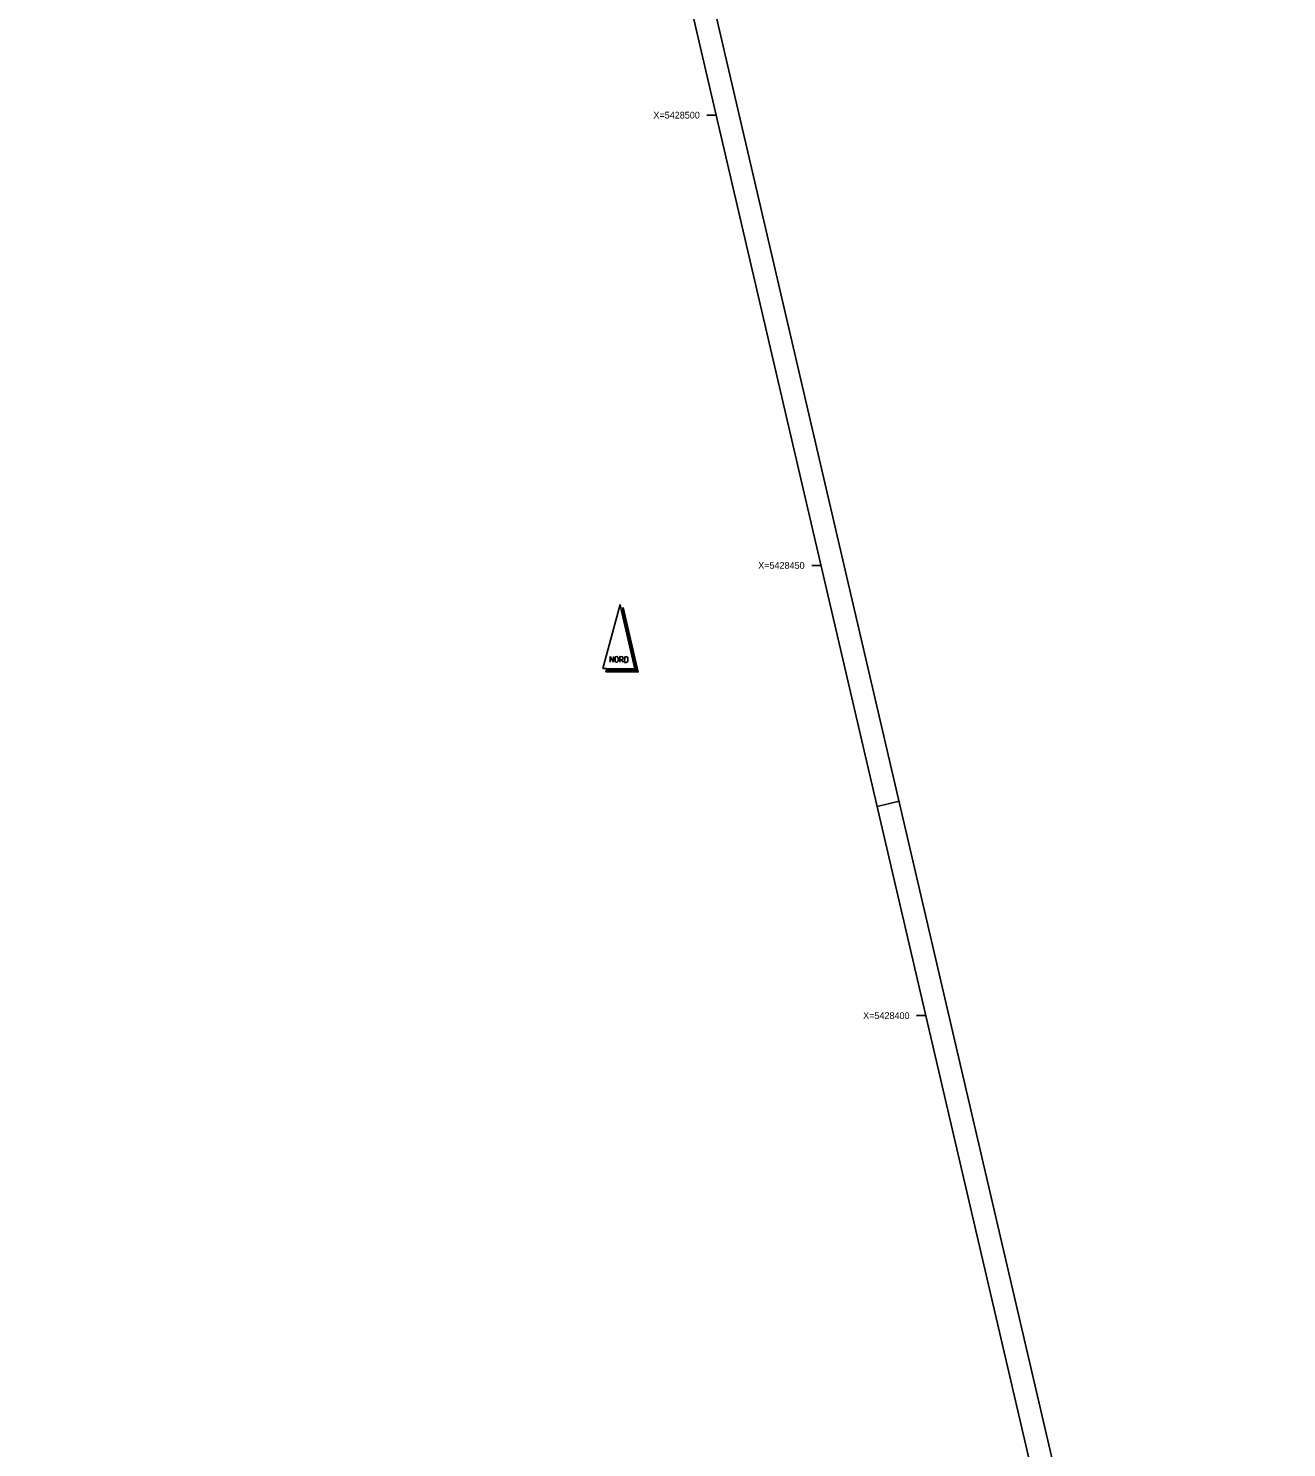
# Model space of a CAD drawing. Extents: x 3455797 to 3456077, y 5428205 to 5428818.
# Drawn here: x 3455936.9 to 3456076.6, y 5428352 to 5428509.6 of the extents above; entities that cross this region are included whole.
import ezdxf

# ---------------------------------------------------------------- set-up
doc = ezdxf.new("R2010")
doc.units = 0
for name, color, linetype in [('_GINETZ', 7, 'Continuous'), ('Nordpfeil', 7, 'Continuous'), ('Planrahmen', 7, 'Continuous')]:
    doc.layers.add(name, color=color, linetype=linetype)

# ---------------------------------------------------------------- blocks, each defined once
blk = doc.blocks.new('_X')
at = {"layer": 'Default'}
for p, q in [((-9.050951, -0.03534), (-9.044004, -0.028392)), ((-9.050951, -0.053017), (-9.029862, -0.031928)), ((-9.050951, -0.070695), (-9.01572, -0.035464)), ((-9.050951, -0.088373), (-9.001578, -0.038999)), ((-9.050951, -0.106051), (-8.987435, -0.042535)), ((-9.050951, -0.123728), (-8.973293, -0.04607)), ((-9.050951, -0.141406), (-8.959151, -0.049606)), ((-9.050951, -0.159084), (-8.948451, -0.056584)), ((-9.050951, -0.176761), (-8.948451, -0.074261)), ((-9.050951, -0.194439), (-8.948451, -0.091939)), ((-9.050951, -0.212117), (-8.948451, -0.109617)), ((-9.050951, -0.229794), (-8.948451, -0.127294)), ((-9.050951, -0.247472), (-8.948451, -0.144972)), ((-9.050951, -0.26515), (-8.948451, -0.16265)), ((-9.050951, -0.282827), (-8.948451, -0.180327)), ((-9.050951, -0.300505), (-8.948451, -0.198005)), ((-9.050951, -0.318183), (-8.948451, -0.215683)), ((-9.050951, -0.33586), (-8.948451, -0.23336)), ((-9.050951, -0.353538), (-8.948451, -0.251038)), ((-9.050951, -0.371216), (-8.948451, -0.268716)), ((-9.050951, -0.388893), (-8.948451, -0.286393)), ((-9.050951, -0.406571), (-8.948451, -0.304071)), ((-9.050951, -0.424249), (-8.948451, -0.321749)), ((-9.050951, -0.441926), (-8.948451, -0.339426)), ((-9.050951, -0.459604), (-8.948451, -0.357104)), ((-9.050951, -0.477282), (-8.948451, -0.374782)), ((-9.050951, -0.494959), (-8.948451, -0.392459)), ((-9.050951, -0.512637), (-8.948451, -0.410137)), ((-9.050951, -0.530315), (-8.948451, -0.427815)), ((-9.050951, -0.547992), (-8.948451, -0.445492)), ((-9.050951, -0.56567), (-8.948451, -0.46317)), ((-9.050951, -0.583348), (-8.948451, -0.480848)), ((-9.050951, -0.601025), (-8.948451, -0.498525)), ((-9.050951, -0.618703), (-8.948451, -0.516203)), ((-9.050951, -0.636381), (-8.948451, -0.533881)), ((-9.050951, -0.654058), (-8.948451, -0.551558)), ((-9.050951, -0.671736), (-8.948451, -0.569236)), ((-9.050951, -0.689414), (-8.948451, -0.586914)), ((-9.050951, -0.707091), (-8.948451, -0.604591)), ((-9.050951, -0.724769), (-8.948451, -0.622269)), ((-9.050951, -0.742447), (-8.948451, -0.639947)), ((-9.050951, -0.760124), (-8.948451, -0.657624)), ((-9.050951, -0.777802), (-8.948451, -0.675302)), ((-9.050951, -0.79548), (-8.948451, -0.69298)), ((-9.050951, -0.813157), (-8.948451, -0.710657)), ((-9.050951, -0.830835), (-8.948451, -0.728335)), ((-9.050951, -0.848513), (-8.948451, -0.746013)), ((-9.050951, -0.86619), (-8.948451, -0.76369)), ((-9.050951, -0.883868), (-8.948451, -0.781368)), ((-9.050951, -0.901546), (-8.948451, -0.799046)), ((-9.050951, -0.919223), (-8.948451, -0.816723)), ((-9.050951, -0.936901), (-8.948451, -0.834401)), ((-9.050951, -0.954579), (-8.948451, -0.852079)), ((-9.050951, -0.972256), (-8.948451, -0.869756)), ((-8.850641, -0.984078), (-8.748141, -0.881578)), ((-8.827071, -0.978186), (-8.724571, -0.875686)), ((-8.803501, -0.972293), (-8.701001, -0.869793)), ((-8.77993, -0.9664), (-8.67743, -0.8639)), ((-8.75636, -0.960508), (-8.65386, -0.858008)), ((-8.73279, -0.954615), (-8.63029, -0.852115)), ((-8.70922, -0.948723), (-8.60672, -0.846223)), ((-8.685649, -0.94283), (-8.583149, -0.84033)), ((-8.662079, -0.936938), (-8.559579, -0.834438)), ((-8.638509, -0.931045), (-8.536009, -0.828545)), ((-8.614939, -0.925153), (-8.512439, -0.822653)), ((-8.591369, -0.91926), (-8.488869, -0.81676)), ((-8.567798, -0.913367), (-8.465298, -0.810867)), ((-8.544228, -0.907475), (-8.441728, -0.804975)), ((-8.520658, -0.901582), (-8.418158, -0.799082)), ((-8.497088, -0.89569), (-8.394588, -0.79319)), ((-8.473517, -0.889797), (-8.371017, -0.787297)), ((-8.449947, -0.883905), (-8.347447, -0.781405)), ((-8.426377, -0.878012), (-8.323877, -0.775512)), ((-8.402807, -0.87212), (-8.300307, -0.76962)), ((-8.379237, -0.866227), (-8.276737, -0.763727)), ((-8.355666, -0.860334), (-8.253166, -0.757834)), ((-8.332096, -0.854442), (-8.229596, -0.751942)), ((-8.308526, -0.848549), (-8.206026, -0.746049)), ((-8.284956, -0.842657), (-8.182456, -0.740157)), ((-8.261385, -0.836764), (-8.158885, -0.734264)), ((-8.237815, -0.830872), (-8.135315, -0.728372)), ((-8.214245, -0.824979), (-8.111745, -0.722479)), ((-8.190675, -0.819087), (-8.088175, -0.716587)), ((-8.167104, -0.813194), (-8.064604, -0.710694)), ((-8.143534, -0.807301), (-8.041034, -0.704801)), ((-8.119964, -0.801409), (-8.017464, -0.698909)), ((-8.096394, -0.795516), (-7.993894, -0.693016)), ((-8.072824, -0.789624), (-7.970324, -0.687124)), ((-8.049253, -0.783731), (-7.946753, -0.681231)), ((-8.025683, -0.777839), (-7.923183, -0.675339)), ((-8.002113, -0.771946), (-7.899613, -0.669446)), ((-7.978543, -0.766054), (-7.876043, -0.663554)), ((-7.954972, -0.760161), (-7.852472, -0.657661)), ((-7.931402, -0.754268), (-7.828902, -0.651768)), ((-7.907832, -0.748376), (-7.805332, -0.645876)), ((-7.884262, -0.742483), (-7.781762, -0.639983)), ((-7.860692, -0.736591), (-7.758192, -0.634091)), ((-7.837121, -0.730698), (-7.734621, -0.628198)), ((-7.813551, -0.724806), (-7.711051, -0.622306)), ((-7.789981, -0.718913), (-7.687481, -0.616413)), ((-7.766411, -0.71302), (-7.663911, -0.61052)), ((-7.74284, -0.707128), (-7.64034, -0.604628)), ((-7.71927, -0.701235), (-7.61677, -0.598735)), ((-7.6957, -0.695343), (-7.5932, -0.592843)), ((-7.67213, -0.68945), (-7.56963, -0.58695)), ((-7.64856, -0.683558), (-7.54606, -0.581058)), ((-7.624989, -0.677665), (-7.522489, -0.575165)), ((-7.601419, -0.671773), (-7.498919, -0.569273)), ((-7.577849, -0.66588), (-7.475349, -0.56338)), ((-7.554279, -0.659987), (-7.451779, -0.557487)), ((-7.530708, -0.654095), (-7.428208, -0.551595)), ((-7.507138, -0.648202), (-7.404638, -0.545702)), ((-7.483568, -0.64231), (-7.381068, -0.53981)), ((-7.459998, -0.636417), (-7.357498, -0.533917)), ((-7.436427, -0.630525), (-7.333927, -0.528025)), ((-7.412857, -0.624632), (-7.310357, -0.522132)), ((-7.389287, -0.61874), (-7.286787, -0.51624)), ((-7.365717, -0.612847), (-7.263217, -0.510347)), ((-7.342147, -0.606954), (-7.239647, -0.504454)), ((-7.318576, -0.601062), (-7.216076, -0.498562)), ((-7.295006, -0.595169), (-7.193384, -0.493547)), ((-7.271436, -0.589277), (-7.179242, -0.497083)), ((-7.247866, -0.583384), (-7.1651, -0.500619)), ((-7.224295, -0.577492), (-7.150958, -0.504154)), ((-7.200725, -0.571599), (-7.136816, -0.50769)), ((-7.177155, -0.565707), (-7.122674, -0.511225)), ((-7.153585, -0.559814), (-7.108531, -0.514761)), ((-7.130015, -0.553921), (-7.094389, -0.518296)), ((-7.106444, -0.548029), (-7.080247, -0.521832)), ((-7.082874, -0.542136), (-7.066105, -0.525367)), ((-7.059304, -0.536244), (-7.051963, -0.528903)), ((-9.050951, -0.989934), (-8.948451, -0.887434)), ((-9.050951, -1.007612), (-8.948451, -0.905112)), ((-9.050951, -1.025289), (-8.948451, -0.922789)), ((-9.039203, -1.031219), (-8.936703, -0.928719)), ((-9.015633, -1.025326), (-8.913133, -0.922826)), ((-8.992062, -1.019433), (-8.889562, -0.916933)), ((-8.968492, -1.013541), (-8.865992, -0.911041)), ((-8.944922, -1.007648), (-8.842422, -0.905148)), ((-8.921352, -1.001756), (-8.818852, -0.899256)), ((-8.897781, -0.995863), (-8.795281, -0.893363)), ((-8.874211, -0.989971), (-8.771711, -0.887471))]:
    blk.add_line(p, q, dxfattribs=at)
blk = doc.blocks.new('SY0181')
at = {"layer": 'Default'}
for p, q in [((0, 0), (-0.238, -0.951)), ((0.029, -0.117), (0, 0)), ((0.048, -0.044), (0.029, -0.117)), ((0.238, -0.951), (0.029, -0.117)), ((0.286, -1), (0.048, -0.044)), ((-0.131, -0.856), (-0.131, -0.773)), ((-0.131, -0.773), (-0.083, -0.856)), ((-0.083, -0.856), (-0.083, -0.773)), ((-0.059, -0.796), (-0.059, -0.832)), ((-0.012, -0.832), (-0.012, -0.796)), ((0.036, -0.773), (0.012, -0.773)), ((0.012, -0.773), (0.012, -0.856)), ((0.036, -0.82), (0.012, -0.82)), ((0.012, -0.82), (0.036, -0.82)), ((0.059, -0.856), (0.036, -0.82)), ((0.083, -0.773), (0.083, -0.856)), ((0.107, -0.773), (0.083, -0.773)), ((0.131, -0.832), (0.131, -0.796)), ((-0.18, -0.951), (-0.238, -0.951)), ((-0.18, -0.951), (-0.193, -1)), ((-0.193, -1), (0.286, -1)), ((-0.18, -0.951), (0.238, -0.951)), ((0.083, -0.856), (0.107, -0.856))]:
    blk.add_line(p, q, dxfattribs=at)
for centre, start, end in [((-0.036, -0.796), 0, 180), ((-0.036, -0.832), 180, 0), ((0.036, -0.796), 270, 90), ((0.107, -0.796), 0, 90), ((0.107, -0.832), 270, 0)]:
    blk.add_arc(centre, 0.0238, start, end, dxfattribs=at)
at = {"layer": 'Default', "xscale": 0.475511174, "yscale": 0.475511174, "rotation": 89.99999999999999}
blk.add_blockref('_X', (-0.205, 3.304), dxfattribs=at)
blk = doc.blocks.new('A$C3D976B1C')
at = {"layer": 'Nordpfeil', "xscale": 15, "yscale": 15.000000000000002, "rotation": 118.32368212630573}
blk.add_blockref('SY0181', (0, 0), dxfattribs=at)

msp = doc.modelspace()

# ---------------------------------------------------------------- linework, layer by layer
at = {"layer": '_GINETZ'}
for p, q in [((3456013.27, 5428500), (3456012.24, 5428500)), ((3456024.91, 5428450), (3456023.88, 5428450)), ((3456036.55, 5428400), (3456035.52, 5428400))]:
    msp.add_line(p, q, dxfattribs=at)
at = {"layer": 'Planrahmen'}
for points in [[(3455797.16, 5428784.32), (3455931.98, 5428205.3), (3456076.61, 5428238.98), (3455941.8, 5428817.99)], [(3455801.86, 5428775.14), (3455933.84, 5428208.31), (3456073.61, 5428240.85), (3455941.63, 5428807.69)]]:
    msp.add_lwpolyline(points, close=True, dxfattribs=at)
msp.add_lwpolyline([(3456033.58, 5428423.8), (3456031.14, 5428423.23)], dxfattribs=at)

# ---------------------------------------------------------------- block references
at = {"layer": 'Nordpfeil', "xscale": 0.5000000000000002, "yscale": 0.5000000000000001, "rotation": -119.41854660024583}
msp.add_blockref('A$C3D976B1C', (3456002.6, 5428445.66), dxfattribs=at)

# ---------------------------------------------------------------- texts
at = {"layer": '_GINETZ'}
for s, p in [('X=5428500', (3456006.29, 5428499.62)), ('X=5428450', (3456017.93, 5428449.62)), ('X=5428400', (3456029.58, 5428399.62))]:
    msp.add_text(s, height=0.75, dxfattribs=at).set_placement(p)

doc.saveas('drawing.dxf')
